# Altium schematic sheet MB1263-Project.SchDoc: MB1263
size A4; Date: Not used; ApprovedBy: Not used; CheckedBy: Not used; Author: Not used; CompanyName: STMicroelectronics; DrawnBy: Not used; Engineer: Not used; Organization: Not used; Address1: Not used; Address2: Not used; Address3: Not used; Address4: Not used; DocumentNumber: Not used; Revision: Not used; SheetNumber: 1; SheetTotal: 11
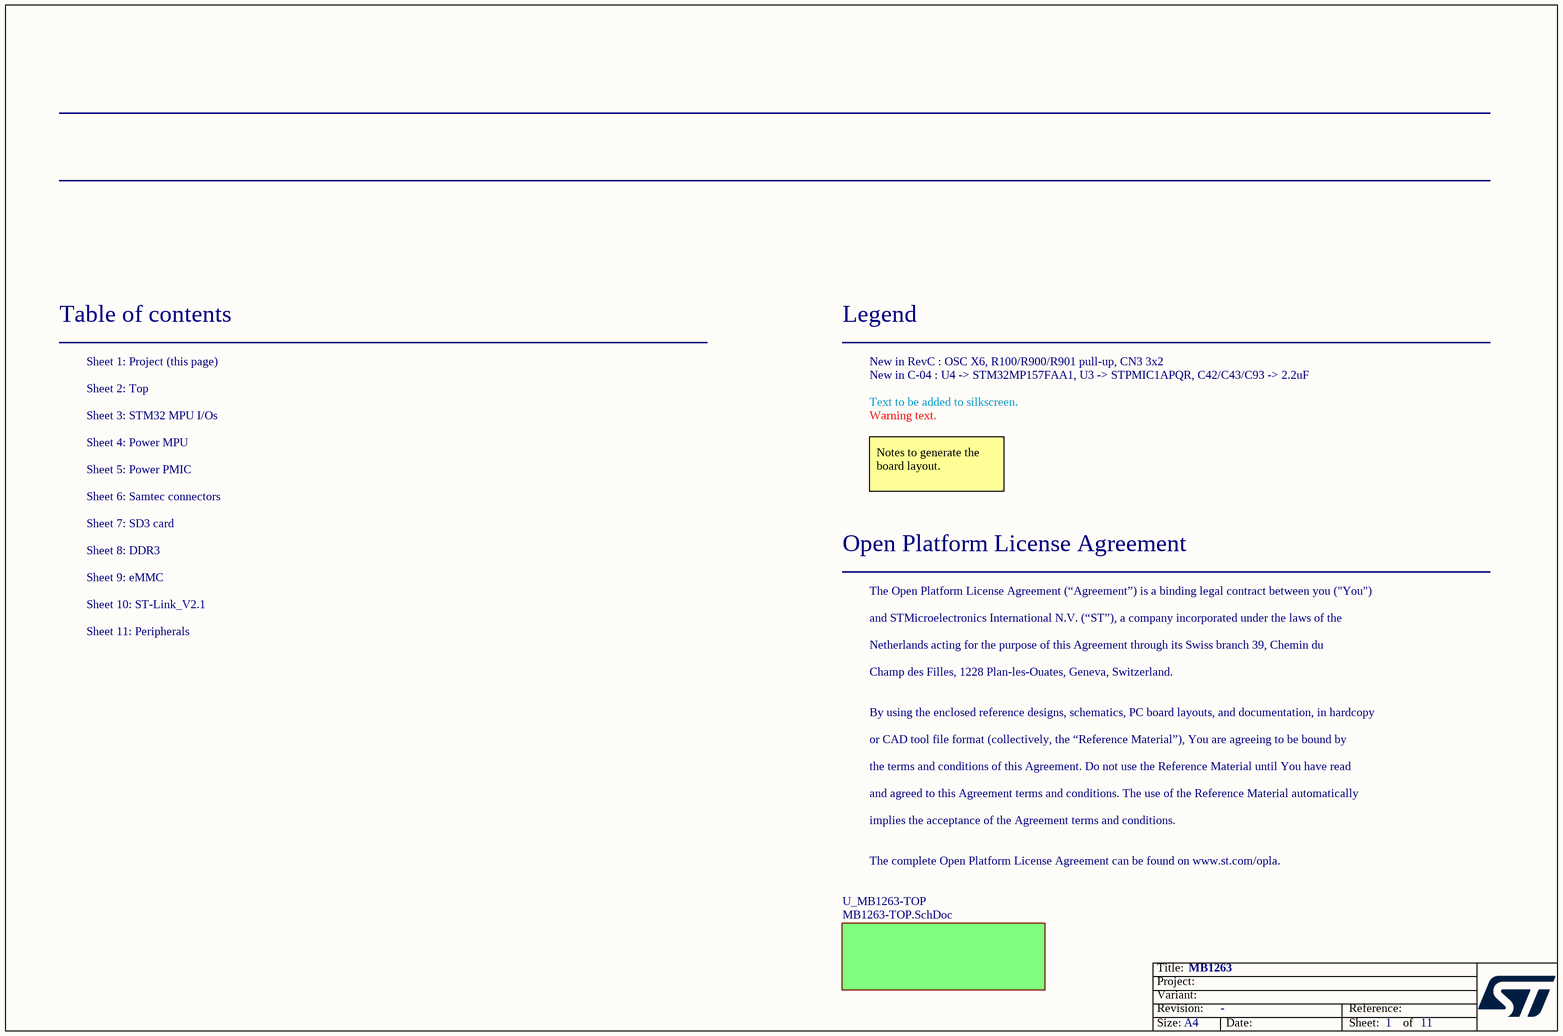
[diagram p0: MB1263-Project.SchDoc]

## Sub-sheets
U_MB1263-TOP = MB1263-TOP.SchDoc: no entries

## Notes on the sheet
- Table of contents
- Sheet 1: Project (this page)
- Legend
- New in RevC : OSC X6, R100/R900/R901 pull-up, CN3 3x2
- New in C-04 : U4 -> STM32MP157FAA1, U3 -> STPMIC1APQR, C42/C43/C93 -> 2.2uF
- Sheet 2: Top
- Sheet 3: STM32 MPU I/Os
- Sheet 4: Power MPU
- Text to be added to silkscreen.
- Warning text.
- Sheet 6: Samtec connectors
- Sheet 5: Power PMIC
- Notes to generate the board layout.
- Sheet 7: SD3 card
- Sheet 9: eMMC
- Sheet 8: DDR3
- Open Platform License Agreement
- Sheet 10: ST-Link_V2.1
- Sheet 11: Peripherals
- The Open Platform License Agreement (“Agreement”) is a binding legal contract between you ("You")
- and STMicroelectronics International N.V. (“ST”), a company incorporated under the laws of the
- Netherlands acting for the purpose of this Agreement through its Swiss branch 39, Chemin du
- Champ des Filles, 1228 Plan-les-Ouates, Geneva, Switzerland.
- By using the enclosed reference designs, schematics, PC board layouts, and documentation, in hardcopy
- or CAD tool file format (collectively, the “Reference Material”), You are agreeing to be bound by
- the terms and conditions of this Agreement. Do not use the Reference Material until You have read
- and agreed to this Agreement terms and conditions. The use of the Reference Material automatically
- implies the acceptance of the Agreement terms and conditions.
- The complete Open Platform License Agreement can be found on www.st.com/opla.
